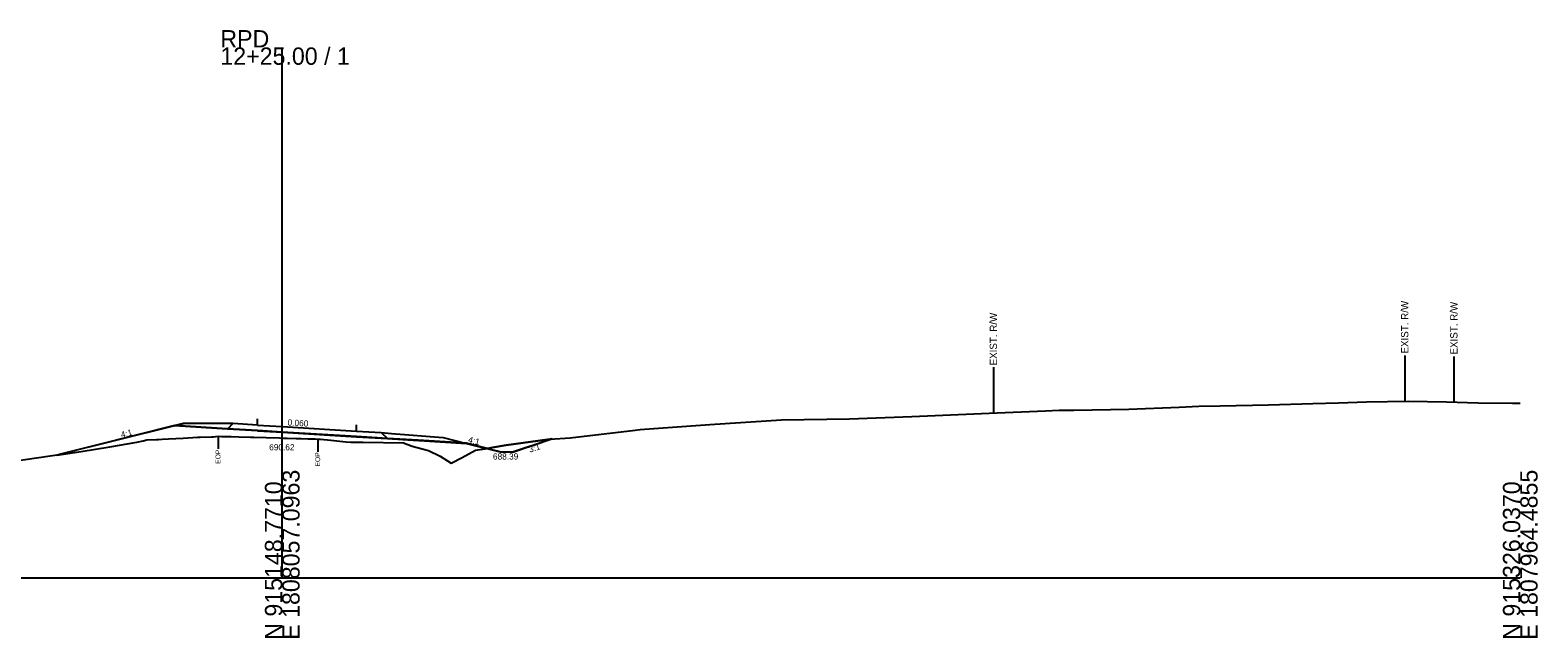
# Model space of a CAD drawing. Extents: x -26 to 403, y -10 to 8517.
# Drawn here: x 159.3 to 402.8, y 4490.3 to 4588.5 of the extents above; entities that cross this region are included whole.
import ezdxf

# ---------------------------------------------------------------- set-up
doc = ezdxf.new("R2010")
doc.units = 0
for name, color, linetype in [('Exist Cross Section Cell', 7, 'Continuous'), ('Exist XS Center Line Elevation Label', 7, 'Continuous'), ('Exist XS Ground Line', 7, 'Continuous'), ('Old_Level_10', 7, 'Continuous'), ('Prop XS Ditch Slope Text', 7, 'Continuous'), ('Prop XS Ditch Standard Text', 7, 'Continuous'), ('Prop XS Earthwork Shape', 7, 'Continuous'), ('Prop XS EOT Tick Mark', 7, 'Continuous'), ('Prop XS Finish Grade', 7, 'Continuous'), ('Prop XS Finish Grade Earthwork', 7, 'Continuous'), ('Prop XS Finish Grade Paved Shoulder', 7, 'Continuous'), ('Prop XS Finish Grade Pavement', 7, 'Continuous'), ('Prop XS Hydro Fill Slope Data', 7, 'Continuous'), ('Prop XS Pvmt Edge Slope', 7, 'Continuous'), ('Prop XS SE Text', 7, 'Continuous'), ('Prop XS Side Slope Text', 7, 'Continuous'), ('Prop XS Subgrade Earthwork', 7, 'Continuous')]:
    doc.layers.add(name, color=color, linetype=linetype)

msp = doc.modelspace()

# ---------------------------------------------------------------- linework, layer by layer
at = {"layer": 'Exist Cross Section Cell'}
for p, q in [((200, 4500), (200, 4585.74)), ((0, 4500), (200, 4500)), ((200, 4500), (400, 4500))]:
    msp.add_line(p, q, dxfattribs=at)
at = {"layer": 'Exist XS Ground Line'}
msp.add_lwpolyline([(156.26, 4518.83), (162.51, 4519.71), (167.54, 4520.44), (172.13, 4521.17), (176.53, 4521.92), (177.55, 4522.18), (178.13, 4522.29), (179.67, 4522.37), (180.03, 4522.39), (180.58, 4522.42), (181.6, 4522.47), (184.01, 4522.61), (186.28, 4522.73), (186.75, 4522.74), (188.55, 4522.81), (188.91, 4522.82), (189.28, 4522.87), (189.62, 4522.89), (190.17, 4522.88), (191.75, 4522.84), (193.01, 4522.8), (194.87, 4522.76), (195.43, 4522.74), (197.39, 4522.69), (199.55, 4522.63), (200.21, 4522.61), (200.81, 4522.6), (202.27, 4522.55), (203.03, 4522.53), (204.12, 4522.49), (205.31, 4522.46), (205.73, 4522.45), (206.19, 4522.41), (207.82, 4522.28), (208.79, 4522.17), (210.28, 4521.97), (211.09, 4521.95), (213.07, 4521.93), (219.58, 4521.81), (220.99, 4521.27), (223.64, 4520.59), (225.53, 4519.66), (227.28, 4518.54), (229.09, 4519.46), (231.21, 4520.64), (233.96, 4521.06), (236.19, 4521.46), (241.28, 4522.18), (243.22, 4522.43), (246.52, 4522.65), (257.01, 4523.89), (257.8, 4523.97), (258.52, 4524.02), (269.08, 4524.77), (280.64, 4525.57), (291.65, 4525.7), (301.71, 4526.08), (302.93, 4526.15), (304.26, 4526.2), (314.21, 4526.62), (323.3, 4527.01), (325.49, 4527.11), (327.89, 4527.12), (336.78, 4527.29), (344.9, 4527.6), (348.06, 4527.76), (351.52, 4527.79), (359.34, 4527.97), (366.5, 4528.17), (370.62, 4528.3), (375.14, 4528.47), (381.91, 4528.58), (388.09, 4528.45), (393.19, 4528.28), (398.77, 4528.26), (400, 4528.26)], dxfattribs=at)
at = {"layer": 'Old_Level_10'}
for p, q in [((381.33, 4535.97), (381.33, 4528.57)), ((389.27, 4535.81), (389.27, 4528.41)), ((314.88, 4534.05), (314.88, 4526.65)), ((189.62, 4522.89), (189.62, 4520.84)), ((205.73, 4522.45), (205.73, 4520.39))]:
    msp.add_line(p, q, dxfattribs=at)
at = {"layer": 'Prop XS Earthwork Shape'}
for points in [[(195.98, 4523.81), (191.13, 4524.1), (182.59, 4524.62), (163.56, 4519.86), (167.54, 4520.44), (172.13, 4521.17), (176.53, 4521.92), (177.55, 4522.18), (178.13, 4522.29), (179.67, 4522.37), (180.03, 4522.39), (180.58, 4522.42), (181.6, 4522.47), (184.01, 4522.61), (186.28, 4522.73), (186.75, 4522.74), (188.55, 4522.81), (188.91, 4522.82), (189.28, 4522.87), (189.62, 4522.89), (190.17, 4522.88), (191.75, 4522.84), (193.01, 4522.8), (194.87, 4522.76), (195.43, 4522.74), (197.39, 4522.69), (199.55, 4522.63), (200.21, 4522.61), (200.81, 4522.6), (202.27, 4522.55), (203.03, 4522.53), (204.12, 4522.49), (205.31, 4522.46), (205.73, 4522.45), (206.19, 4522.41), (207.82, 4522.28), (208.79, 4522.17), (210.28, 4521.97), (211.09, 4521.95), (213.07, 4521.93), (219.58, 4521.81), (220.99, 4521.27), (223.64, 4520.59), (225.53, 4519.66), (227.28, 4518.54), (229.09, 4519.46), (231.21, 4520.64), (233.17, 4520.94), (229.78, 4521.79), (221.97, 4522.25), (216.98, 4522.55), (211.98, 4522.85), (199.98, 4523.57)], [(237.36, 4520.39), (243.57, 4522.46), (243.22, 4522.43), (241.28, 4522.18), (236.19, 4521.46), (233.96, 4521.06), (233.17, 4520.94), (235.36, 4520.39)]]:
    msp.add_lwpolyline(points, close=True, dxfattribs=at)
at = {"layer": 'Prop XS EOT Tick Mark'}
for p, q in [((196, 4524.69), (196, 4525.69)), ((212, 4523.73), (212, 4524.73))]:
    msp.add_line(p, q, dxfattribs=at)
at = {"layer": 'Prop XS Finish Grade'}
for p, q in [((182.59, 4524.58), (184, 4524.93)), ((182.59, 4524.58), (182.59, 4524.58)), ((190.43, 4524.93), (184, 4524.93)), ((192, 4524.93), (190.43, 4524.93)), ((216, 4523.49), (217.64, 4523.36)), ((217.64, 4523.36), (226, 4522.69)), ((226, 4522.69), (226, 4522.69)), ((226, 4522.69), (229.78, 4521.75))]:
    msp.add_line(p, q, dxfattribs=at)
at = {"layer": 'Prop XS Finish Grade Earthwork'}
for p, q in [((182.59, 4524.58), (163.94, 4519.92)), ((229.78, 4521.75), (235.2, 4520.39)), ((237.2, 4520.39), (243.37, 4522.44)), ((235.2, 4520.39), (237.2, 4520.39))]:
    msp.add_line(p, q, dxfattribs=at)
at = {"layer": 'Prop XS Finish Grade Paved Shoulder'}
for p, q in [((196, 4524.69), (192, 4524.93)), ((212, 4523.73), (216, 4523.49))]:
    msp.add_line(p, q, dxfattribs=at)
at = {"layer": 'Prop XS Finish Grade Pavement'}
for p, q in [((196, 4524.69), (200, 4524.45)), ((200, 4524.45), (212, 4523.73))]:
    msp.add_line(p, q, dxfattribs=at)
at = {"layer": 'Prop XS Hydro Fill Slope Data'}
msp.add_line((184, 4524.93), (163.94, 4519.92), dxfattribs=at)
at = {"layer": 'Prop XS Pvmt Edge Slope'}
for p, q in [((192, 4524.93), (191.13, 4524.06)), ((216, 4523.49), (216.98, 4522.51))]:
    msp.add_line(p, q, dxfattribs=at)
at = {"layer": 'Prop XS Subgrade Earthwork'}
for p, q in [((191.13, 4524.06), (182.59, 4524.58)), ((195.98, 4523.77), (191.13, 4524.06)), ((195.98, 4523.77), (199.98, 4523.53)), ((199.98, 4523.53), (211.98, 4522.81)), ((211.98, 4522.81), (216.98, 4522.51)), ((216.98, 4522.51), (221.97, 4522.21)), ((216.98, 4522.51), (229.78, 4521.75))]:
    msp.add_line(p, q, dxfattribs=at)

# ---------------------------------------------------------------- texts
at = {"layer": 'Exist Cross Section Cell'}
for s, p in [('RPD', (190, 4585.74)), ('12+25.00 / 1', (190, 4582.94))]:
    msp.add_text(s, height=2.8, dxfattribs=at).set_placement(p)
for s, p in [('E 1808057.0963', (202.8, 4490)), ('E 1807964.4855', (402.8, 4490)), ('N 915148.7710', (200, 4490)), ('N 915326.0370', (400, 4490))]:
    msp.add_text(s, height=2.8, rotation=90, dxfattribs=at).set_placement(p)
at = {"layer": 'Exist XS Center Line Elevation Label'}
msp.add_text('690.62', height=1, dxfattribs=at).set_placement((197.89, 4520.62))
at = {"layer": 'Old_Level_10'}
for s, height, rotation, p in [('EXIST. R/W', 1.181, 90, (315.47, 4534.35)), ('EXIST. R/W', 1.181, 90, (381.92, 4536.27)), ('EXIST. R/W', 1.181, 90, (389.86, 4536.11)), ('3:1', 1, 18.4349, (240.01, 4520.23)), ('EOP', 0.787, 90, (190.01, 4518.44)), ('EOP', 0.787, 90, (206.12, 4518))]:
    msp.add_text(s, height=height, rotation=rotation, dxfattribs=at).set_placement(p)
at = {"layer": 'Prop XS Ditch Slope Text'}
msp.add_text('4:1', height=1, rotation=345.9638, dxfattribs=at).set_placement((229.96, 4521.9))
at = {"layer": 'Prop XS Ditch Standard Text'}
msp.add_text('688.39', height=1, dxfattribs=at).set_placement((234.04, 4519.13))
at = {"layer": 'Prop XS SE Text'}
msp.add_text('0.060', height=1, rotation=356.5664, dxfattribs=at).set_placement((200.84, 4524.64))
at = {"layer": 'Prop XS Side Slope Text'}
msp.add_text('4:1', height=1, rotation=14.0362, dxfattribs=at).set_placement((174.05, 4522.63))

doc.saveas('drawing.dxf')
